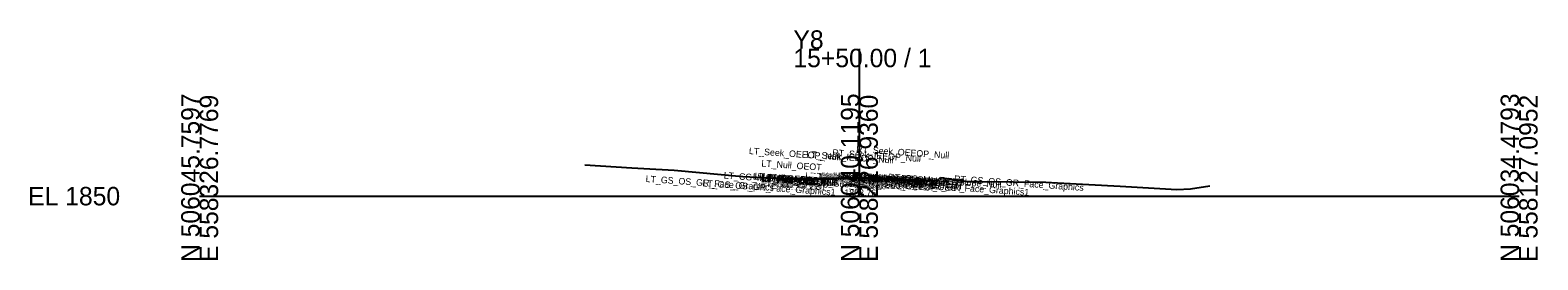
# Model space of a CAD drawing. Extents: x -26 to 203, y -10 to 8070.
# Drawn here: x -25.7 to 202.8, y 5490.3 to 5525.2 of the extents above; entities that cross this region are included whole.
import ezdxf

# ---------------------------------------------------------------- set-up
doc = ezdxf.new("R2010")
doc.units = 0
for name, color, linetype in [('Default', 7, 'Continuous'), ('Exist Cross Section Cell', 7, 'Continuous'), ('Exist XS Center Line Elevation Label', 7, 'Continuous'), ('Exist XS Ground Line', 7, 'Continuous'), ('Prop CMT Pvmt Course 1', 7, 'Continuous'), ('Prop CMT Pvmt Surface', 7, 'Continuous'), ('Prop XS Earthwork Shape', 7, 'Continuous'), ('Typical Text Grade Point CELL', 7, 'Continuous')]:
    doc.layers.add(name, color=color, linetype=linetype)

msp = doc.modelspace()

# ---------------------------------------------------------------- linework, layer by layer
at = {"layer": 'Exist Cross Section Cell'}
for p, q in [((100, 5500), (100, 5522.39)), ((0, 5500), (100, 5500)), ((100, 5500), (200, 5500))]:
    msp.add_line(p, q, dxfattribs=at)
at = {"layer": 'Exist XS Ground Line'}
for p, q in [((58.38, 5504.74), (65.51, 5504.3)), ((65.51, 5504.3), (67.32, 5504.21)), ((67.32, 5504.21), (71.92, 5503.93)), ((71.92, 5503.93), (82.31, 5502.96)), ((82.31, 5502.96), (85.54, 5502.81)), ((85.54, 5502.81), (89.69, 5502.63)), ((89.69, 5502.63), (94.41, 5502.69)), ((94.41, 5502.69), (100.16, 5502.76)), ((100.16, 5502.76), (104.83, 5502.64)), ((104.83, 5502.64), (110.41, 5502.42)), ((110.41, 5502.42), (111.13, 5502.36)), ((111.13, 5502.36), (111.64, 5502.34)), ((111.64, 5502.34), (111.97, 5502.55)), ((111.97, 5502.55), (112.31, 5502.84)), ((112.31, 5502.84), (116.29, 5502.2)), ((116.29, 5502.2), (118.38, 5502.22)), ((118.38, 5502.22), (128.24, 5502.12)), ((128.24, 5502.12), (130.04, 5502.02)), ((130.04, 5502.02), (139.55, 5501.5)), ((139.55, 5501.5), (148.11, 5501)), ((148.11, 5501), (150.17, 5501.11)), ((150.17, 5501.11), (153.11, 5501.57))]:
    msp.add_line(p, q, dxfattribs=at)
at = {"layer": 'Prop CMT Pvmt Course 1'}
msp.add_lwpolyline([(100, 5502.76), (102, 5502.71), (102.01, 5502.71), (105.99, 5502.6), (106, 5502.6), (110.5, 5502.42)], dxfattribs=at)
at = {"layer": 'Prop CMT Pvmt Surface'}
for points in [[(100, 5502.76), (98, 5502.73), (97.99, 5502.73), (89.68, 5502.63)], [(100, 5502.76), (102, 5502.71), (102.01, 5502.71), (105.99, 5502.6), (106, 5502.6), (110.5, 5502.42)]]:
    msp.add_lwpolyline(points, dxfattribs=at)
at = {"layer": 'Prop XS Earthwork Shape'}
for points in [[(100, 5502.76), (102, 5502.71), (105.99, 5502.6), (110.5, 5502.42), (110.5, 5502.29), (100, 5502.63), (89.68, 5502.5), (89.68, 5502.63), (94.41, 5502.69), (98, 5502.73)], [(104.83, 5502.64), (105.99, 5502.6), (102, 5502.71), (100, 5502.76), (100.16, 5502.76)]]:
    msp.add_lwpolyline(points, close=True, dxfattribs=at)

# ---------------------------------------------------------------- texts
at = {"layer": 'Default'}
msp.add_text('-', height=0.0001, dxfattribs=at).set_placement((0, 5500))
at = {"layer": 'Exist Cross Section Cell'}
for s, p in [('Y8', (90, 5522.39)), ('15+50.00 / 1', (90, 5519.59)), ('EL 1850', (-26, 5498.6))]:
    msp.add_text(s, height=2.8, dxfattribs=at).set_placement(p)
for s, p in [('N 506045.7597', (0, 5490)), ('E 558326.7769', (2.8, 5490)), ('N 506040.1195', (100, 5490)), ('E 558226.9360', (102.8, 5490)), ('N 506034.4793', (200, 5490)), ('E 558127.0952', (202.8, 5490))]:
    msp.add_text(s, height=2.8, rotation=90, dxfattribs=at).set_placement(p)
at = {"layer": 'Exist XS Center Line Elevation Label'}
msp.add_text('1852.76', height=1, dxfattribs=at).set_placement((97.72, 5500.01))
at = {"layer": 'Typical Text Grade Point CELL'}
for s, p in [('RT_Seek_OEEOP_Null', (99.49, 5506.66)), ('LT_Seek_OEEOP_Null', (83.23, 5506.4)), ('LT_Null_OEOT', (85.12, 5504.51)), ('LT_Seek_IEEOP_Null', (91.93, 5505.88)), ('RT_Seek_IEEOP_Null', (95.87, 5506.13)), ('LT_GS_OS_GR_Face_Graphics', (67.58, 5502.15)), ('LT_CG_MatchPVSlope_Null', (79.42, 5502.67)), ('LT_PV_Sub_Tie_Out', (83.83, 5502.54)), ('LT_Null OEEOP Test', (84.08, 5502.56)), ('LT_PV2_OEEOP', (85.05, 5502.2)), ('LT_PV1_OEEOP', (85.17, 5502.32)), ('LT_PV2_OEOT', (85.22, 5502.18)), ('LT_PV1_OEOT', (85.34, 5502.42)), ('LT_Pvmt Out', (85.93, 5502.39)), ('LT_Null IEEOP Test', (91.78, 5502.63)), ('LT_PV_Sub_Tie_In', (92.76, 5502.6)), ('LT_PV2_IEEOP', (93.75, 5502.28)), ('LT_PV1_IEEOP', (93.87, 5502.4)), ('Null RT Pvmt Slope', (94.26, 5502.67)), ('Null LT Pvmt Slope', (94.32, 5502.65)), ('PV1_Overlay_Null', (94.75, 5502.5)), ('LT_Pvmt In', (94.84, 5502.45)), ('RT_PV_Sub_Tie_In', (96.7, 5502.58)), ('RT_Null IEEOP Test', (96.72, 5502.6)), ('PV2_PGL', (97.32, 5502.19)), ('PV1_PGL', (97.44, 5502.44)), ('RT_PV2_IEEOP', (97.69, 5502.24)), ('RT_PV1_IEEOP', (97.81, 5502.36)), ('RT_Pvmt In', (98.8, 5502.44)), ('CL', (99.2, 5502.26)), ('RT_Null OEEOP Test', (99.34, 5502.55)), ('RT_PV_Sub_Tie_Out', (100.09, 5502.51)), ('RT_PV2_OEEOP', (101.31, 5502.14)), ('RT_PV1_OEEOP', (101.43, 5502.26)), ('RT_Pvmt Out', (102.17, 5502.36)), ('RT_CG_MatchPVSlope_Null', (104.37, 5502.42)), ('RT_PV1_OEOT', (106.28, 5502.21)), ('RT_GS_OS_GR_Face_Graphics', (114.32, 5502.16)), ('LT_GS_OS_GR_Face_Graphics1', (76.18, 5501.49)), ('LT_PV3_OEEOP', (85.05, 5501.95)), ('LT_Sub_OEEOP', (85.07, 5501.58)), ('LT_PV3_OEOT', (85.22, 5501.93)), ('LT_Sub_OEOT', (85.24, 5501.55)), ('LT_PV3_IEEOP', (93.75, 5502.03)), ('LT_Sub_IEEOP', (93.77, 5501.65)), ('Sub_PGL', (97.35, 5501.57)), ('PV3_PGL', (97.32, 5501.94)), ('RT_PV3_IEEOP', (97.69, 5501.99)), ('RT_Sub_IEEOP', (97.71, 5501.62)), ('RT_PV3_OEEOP', (101.31, 5501.89)), ('RT_Sub_OEEOP', (101.33, 5501.51)), ('RT_GS_OS_GR_Face_Graphics1', (105.32, 5501.49)), ('RT_PV2_OEOT', (106.16, 5501.97)), ('RT_PV3_OEOT', (106.16, 5501.72)), ('RT_Sub_OEOT', (106.19, 5501.34))]:
    msp.add_text(s, height=1, rotation=356, dxfattribs=at).set_placement(p)

doc.saveas('drawing.dxf')
